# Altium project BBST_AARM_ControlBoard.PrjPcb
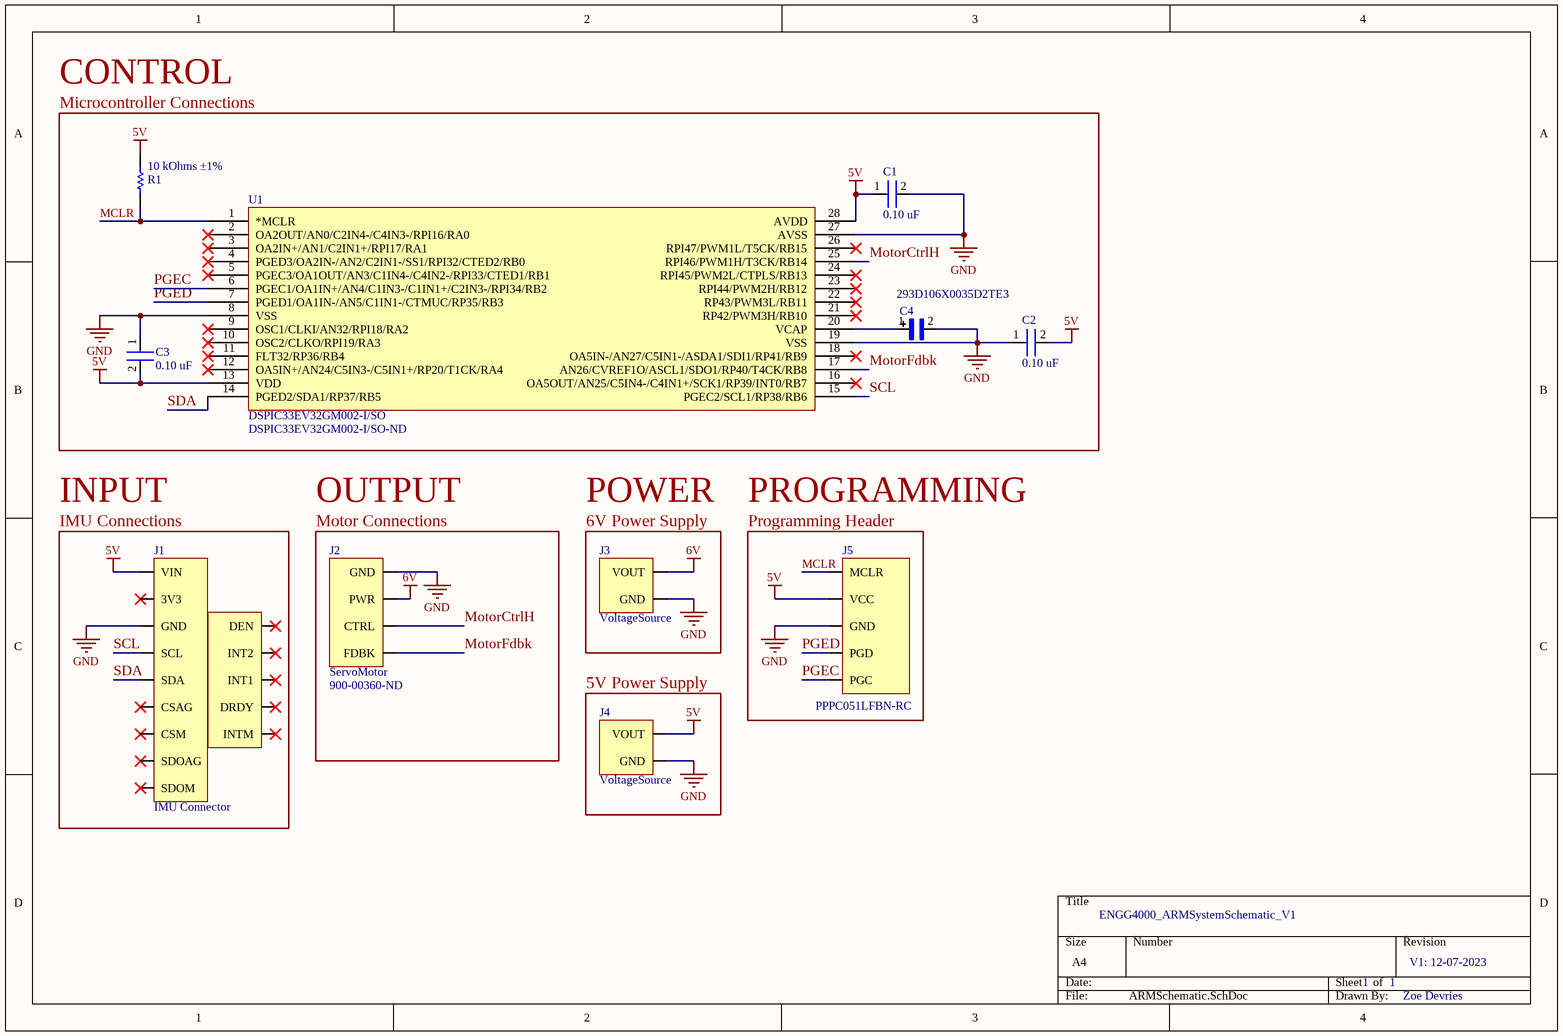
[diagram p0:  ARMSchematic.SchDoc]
1 sheet, 11 parts. Net scope: global (net labels, ports and power ports of the same name join across sheets).
Board file:  ARMPCB.PcbDoc

## Sheet  ARMSchematic.SchDoc
size A4

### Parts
C1  0.10 uF  [CAPC17595_95N_KEM]
C2  0.10 uF  [CAPC17595_95N_KEM]
C3  0.10 uF  [CAPC17595_95N_KEM]
C4  293D106X0035D2TE3  [CAPPM7343X310N]
J1  IMU Connector  [IMU Connector]
J2  ServoMotor  Supplier Part Number 1: 900-00360-ND  [CONN_PPPC041LFBN-RC_SUL]
J3  VoltageSource  [CONN2_5-3021_MOL]
J4  VoltageSource  [CONN2_5-3021_MOL]
J5  PPPC051LFBN-RC  [CONN_PPPC051LFBN-RC_SUL]
R1  value 10 kOhms ±1%  [RNCP0805FTD10K0_V2]  (hidden comment: RNCP0805FTD10K0)
U1  DSPIC33EV32GM002-I/SO  Supplier Part Number 1: DSPIC33EV32GM002-I/SO-ND  [SOIC127P1030X265-28N]

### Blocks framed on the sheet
Microcontroller Connections: C1-C4 R1 U1
IMU Connections: J1
Motor Connections: J2
6V Power Supply: J3
Programming Header: J5
5V Power Supply: J4

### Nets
5V: C1.1 C2.2 C3.2 J1.1(VIN) J4.1(VOUT) J5.2(VCC) R1.2 U1.13(VDD) U1.28(AVDD)
6V: J2.2(PWR) J3.1(VOUT)
GND: C1.2 C2.1 C3.1 C4.2 J1.3(GND) J2.1(GND) J3.2(GND) J4.2(GND) J5.3(GND) U1.8(VSS) U1.19(VSS) U1.27(AVSS)
MCLR: J5.1(MCLR) R1.1 U1.1(*MCLR)
MotorCtrlH: J2.3(CTRL) U1.25(RPI46/PWM1H/T3CK/RB14)
MotorFdbk: J2.4(FDBK) U1.17(AN26/CVREF1O/ASCL1/SDO1/RP40/T4CK/RB8)
PGEC: J5.5(PGC) U1.6(PGEC1/OA1IN+/AN4/C1IN3-/C1IN1+/C2IN3-/RPI34/RB2)
PGED: J5.4(PGD) U1.7(PGED1/OA1IN-/AN5/C1IN1-/CTMUC/RP35/RB3)
SCL: J1.4(SCL) U1.15(PGEC2/SCL1/RP38/RB6)
SDA: J1.5(SDA) U1.14(PGED2/SDA1/RP37/RB5)
NetC4_1: C4.1 U1.20(VCAP)

Not connected (* = marked no-connect by the designer): J1 2(3V3)* 6(CSAG)* 7(CSM)* 8(SDOAG)* 9(SDOM)* 10(DEN)* 11(INT2)* 12(INT1)* 13(DRDY)* 14(INTM)*; U1 2(OA2OUT/AN0/C2IN4-/C4IN3-/RPI16/RA0)* 3(OA2IN+/AN1/C2IN1+/RPI17/RA1)* 4(PGED3/OA2IN-/AN2/C2IN1-/SS1/RPI32/CTED2/RB0)* 5(PGEC3/OA1OUT/AN3/C1IN4-/C4IN2-/RPI33/CTED1/RB1)* 9(OSC1/CLKI/AN32/RPI18/RA2)* 10(OSC2/CLKO/RPI19/RA3)* 11(FLT32/RP36/RB4)* 12(OA5IN+/AN24/C5IN3-/C5IN1+/RP20/T1CK/RA4)* 16(OA5OUT/AN25/C5IN4-/C4IN1+/SCK1/RP39/INT0/RB7)* 18(OA5IN-/AN27/C5IN1-/ASDA1/SDI1/RP41/RB9)* 21(RP42/PWM3H/RB10)* 22(RP43/PWM3L/RB11)* 23(RPI44/PWM2H/RB12)* 24(RPI45/PWM2L/CTPLS/RB13)* 26(RPI47/PWM1L/T5CK/RB15)*

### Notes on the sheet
- CONTROL
- INPUT
- OUTPUT
- POWER
- PROGRAMMING
- ENGG4000_ARMSystemSchematic_V1
- 1
- V1: 12-07-2023
- Zoe Devries

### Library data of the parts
C1-C3 = CerCap: CAP CER 0.1UF; Manufacturer: KEMET; Manufacturer Part Number: C0603C104K5RACTU; Tolerance: 0.1; Temperature Coefficient: 30ppm/°C; Material: Ceramic; Automotive Grade: Grade 1; Voltage Rating: 50 V; Capacitance: 0.10 μF; Temperature Characteristic: X7R
C4 = 293D106X0035D2TE3: Capacitor: tantalum; 10uF; 35VDC; SMD; Case: D; Â±20%; -55Ã·125Â°C; MF: {'manufacturer': u'Vishay Sprague'}
J1 = IMU Connector: LSM9DS1 ACCEL/MAG/GYRO/TEMP BRD Connections
J5 = PPPC051LFBN-RC: Female, 5 C, Straight, .100"CC; 3.20mm Tail, No Mounting; PBT, Phos. Bronze, 105 C; Manufacturer: Sullins; Number of Positions: 5; Connector Type: Header; Pitch: 0.1inch
R1 = CMP-005-000019-1: RES 10K OHM 1% 1/4W 0805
